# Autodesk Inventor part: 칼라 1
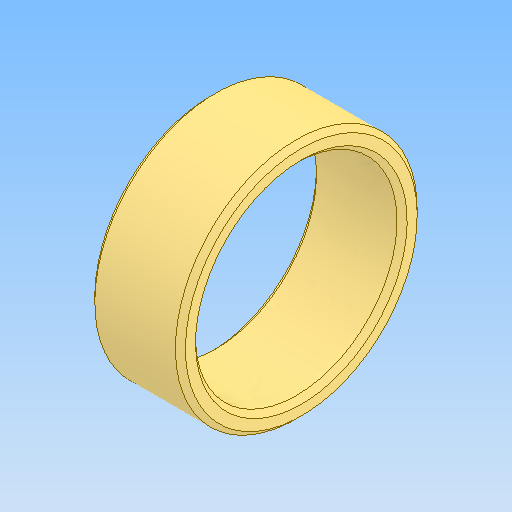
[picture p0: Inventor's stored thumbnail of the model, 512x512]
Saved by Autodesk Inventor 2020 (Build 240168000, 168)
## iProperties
Created: 2025-11
Part Number: 칼라 1
Material: 강철, 연강
Document SubType Name: Modeling
Designer: PC2-06
Density: 7.85 g/cm^3
Appearance: 기본값
Author: jhkim
Sending System: Autodesk Inventor 2026
Preprocessor: ST-DEVELOPER v20.1
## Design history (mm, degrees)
feature "솔리드1"
node "솔리드2"
